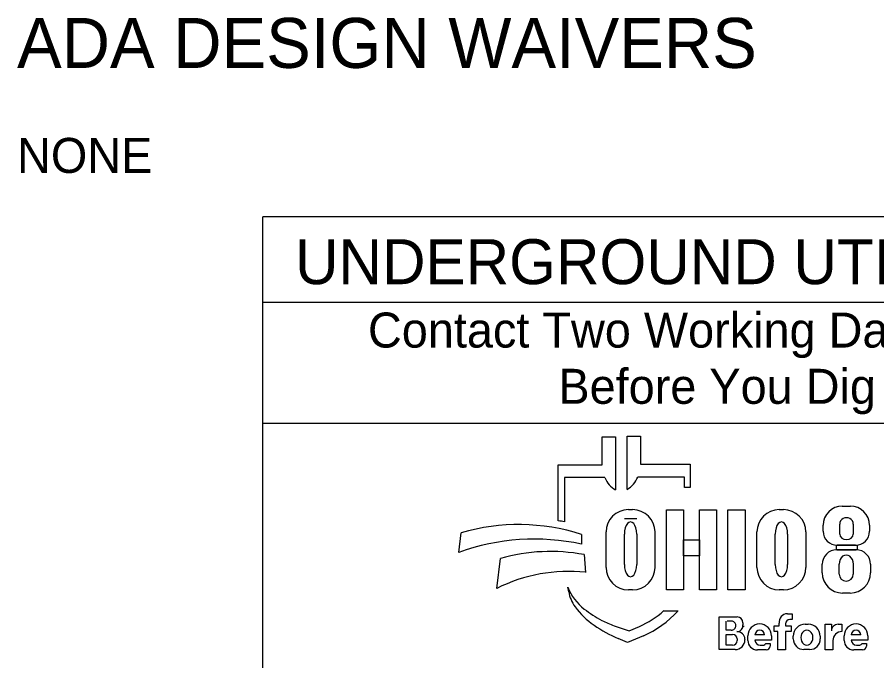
# Model space of a CAD drawing. Extents: x -59 to 82, y -3 to 49.
# Drawn here: x -55.003 to -51.567, y 31.095 to 33.67 of the extents above; entities that cross this region are included whole.
import ezdxf

# ---------------------------------------------------------------- set-up
doc = ezdxf.new("R2010")
doc.units = 0
doc.layers.add('SH_Data', color=7, linetype='Continuous')
doc.layers.add('SH_Text', color=7, linetype='Continuous')

msp = doc.modelspace()

# ---------------------------------------------------------------- linework, layer by layer
at = {"layer": 'SH_Data'}
for p, q in [((-54.0205, 30.534), (-54.0205, 32.8715)), ((-49.7705, 32.8715), (-54.0205, 32.8715)), ((-54.0205, 32.53), (-49.7705, 32.53)), ((-54.0205, 32.0466), (-49.7705, 32.0466))]:
    msp.add_line(p, q, dxfattribs=at)
at = {"layer": 'SH_Text'}
for p, q in [((-52.5651, 31.7813), (-52.5651, 31.9934)), ((-52.5651, 31.9934), (-52.5115, 31.9934)), ((-52.5115, 31.9934), (-52.5115, 31.8819)), ((-52.6644, 31.8795), (-52.6644, 31.991)), ((-52.6644, 31.991), (-52.6108, 31.991)), ((-52.6108, 31.991), (-52.6108, 31.779)), ((-52.8404, 31.6557), (-52.8404, 31.8795)), ((-52.8404, 31.8795), (-52.6644, 31.8795)), ((-52.5115, 31.8819), (-52.3123, 31.8819)), ((-52.3123, 31.8819), (-52.3123, 31.7881)), ((-52.8152, 31.8281), (-52.8152, 31.6513)), ((-52.654, 31.8281), (-52.8152, 31.8281)), ((-52.3355, 31.8304), (-52.5219, 31.8304)), ((-52.3355, 31.7881), (-52.3355, 31.8304)), ((-52.3123, 31.7881), (-52.3355, 31.7881)), ((-52.5595, 31.7004), (-52.5429, 31.7004)), ((-51.9564, 31.7004), (-51.9399, 31.7004)), ((-51.7049, 31.7144), (-51.6721, 31.7144)), ((-52.5262, 31.6633), (-52.576, 31.6633)), ((-51.7812, 31.6137), (-51.7812, 31.638)), ((-51.715, 31.6024), (-51.715, 31.6417)), ((-51.6609, 31.6417), (-51.6609, 31.6024)), ((-51.5958, 31.638), (-51.5958, 31.6137)), ((-53.2378, 31.5294), (-53.2284, 31.6075)), ((-52.7471, 31.601), (-52.7471, 31.5622)), ((-52.6489, 31.4689), (-52.6489, 31.6109)), ((-52.576, 31.4803), (-52.576, 31.6026)), ((-52.5262, 31.6026), (-52.5262, 31.4803)), ((-52.4535, 31.6109), (-52.4535, 31.4689)), ((-52.0459, 31.4689), (-52.0459, 31.6109)), ((-51.973, 31.4803), (-51.973, 31.6026)), ((-51.9232, 31.6026), (-51.9232, 31.4803)), ((-51.8504, 31.6109), (-51.8504, 31.4689)), ((-51.6518, 31.5578), (-51.7252, 31.5578)), ((-52.7371, 31.5204), (-52.7309, 31.4494)), ((-51.727, 31.5394), (-51.6497, 31.5394)), ((-53.0859, 31.3848), (-53.0713, 31.505)), ((-51.7849, 31.4475), (-51.7849, 31.4816)), ((-51.7174, 31.4416), (-51.7174, 31.4825)), ((-51.6606, 31.4825), (-51.6606, 31.4416)), ((-51.5918, 31.4816), (-51.5918, 31.4475)), ((-52.7983, 31.3719), (-52.8013, 31.3898)), ((-52.5429, 31.3794), (-52.5595, 31.3794)), ((-51.9399, 31.3794), (-51.9564, 31.3794)), ((-51.6728, 31.3666), (-51.7039, 31.3666)), ((-52.418, 31.296), (-52.3605, 31.296)), ((-52.1967, 31.1403), (-52.1967, 31.271)), ((-52.1967, 31.271), (-52.1255, 31.271)), ((-51.9241, 31.2838), (-51.9046, 31.2838)), ((-51.9046, 31.2838), (-51.9046, 31.2608)), ((-52.1687, 31.2175), (-52.1687, 31.2545)), ((-52.1435, 31.2545), (-52.1648, 31.2545)), ((-52.1017, 31.2473), (-52.1017, 31.2394)), ((-51.9574, 31.2354), (-51.9574, 31.2459)), ((-51.9313, 31.2439), (-51.9313, 31.2354)), ((-51.9046, 31.2603), (-51.9148, 31.2603)), ((-51.8529, 31.242), (-51.8407, 31.242)), ((-51.7726, 31.1391), (-51.7726, 31.2418)), ((-51.7726, 31.2418), (-51.7481, 31.2418)), ((-51.7481, 31.2418), (-51.7481, 31.2149)), ((-51.7208, 31.2418), (-51.7069, 31.2418)), ((-51.7069, 31.2418), (-51.7069, 31.2121)), ((-52.6164, 31.2357), (-52.557, 31.2152)), ((-52.557, 31.2152), (-52.5159, 31.233)), ((-52.1493, 31.2175), (-52.1687, 31.2175)), ((-51.9767, 31.2124), (-51.9767, 31.2354)), ((-51.9767, 31.2354), (-51.9574, 31.2354)), ((-51.9618, 31.2124), (-51.9767, 31.2124)), ((-51.9618, 31.1391), (-51.9618, 31.2124)), ((-51.9313, 31.2354), (-51.9097, 31.2354)), ((-51.9097, 31.2124), (-51.9313, 31.2124)), ((-51.9313, 31.2124), (-51.9313, 31.1391)), ((-51.9097, 31.2354), (-51.9097, 31.2124)), ((-52.563, 31.1682), (-52.6003, 31.1846)), ((-52.4997, 31.1956), (-52.563, 31.1682)), ((-52.1687, 31.1581), (-52.1687, 31.201)), ((-52.1687, 31.201), (-52.1432, 31.201)), ((-52.125, 31.1829), (-52.125, 31.1765)), ((-52.0937, 31.18), (-52.0937, 31.1796)), ((-52.0821, 31.1771), (-52.0821, 31.1955)), ((-52.0155, 31.1995), (-52.0541, 31.1995)), ((-51.9876, 31.1778), (-52.054, 31.1778)), ((-51.9876, 31.1955), (-51.9876, 31.1778)), ((-51.9007, 31.1834), (-51.9007, 31.1942)), ((-51.7929, 31.1942), (-51.7929, 31.1834)), ((-51.7421, 31.1772), (-51.7421, 31.1391)), ((-51.6972, 31.1771), (-51.6972, 31.1955)), ((-51.6306, 31.1995), (-51.6692, 31.1995)), ((-51.6027, 31.1778), (-51.6691, 31.1778)), ((-51.6027, 31.1955), (-51.6027, 31.1778)), ((-52.133, 31.1403), (-52.1967, 31.1403)), ((-52.1434, 31.1581), (-52.1687, 31.1581)), ((-52.0088, 31.1391), (-52.0442, 31.1391)), ((-52.0331, 31.1586), (-52.019, 31.1586)), ((-52.0104, 31.1641), (-51.9935, 31.1641)), ((-51.9935, 31.1641), (-51.9935, 31.1543)), ((-51.9313, 31.1391), (-51.9618, 31.1391)), ((-51.8357, 31.1406), (-51.8579, 31.1406)), ((-51.7421, 31.1391), (-51.7726, 31.1391)), ((-51.6238, 31.1391), (-51.6592, 31.1391)), ((-51.6482, 31.1586), (-51.6341, 31.1586)), ((-51.6255, 31.1641), (-51.6086, 31.1641)), ((-51.6086, 31.1641), (-51.6086, 31.1543))]:
    msp.add_line(p, q, dxfattribs=at)
for points in [[(-52.407, 31.6993), (-52.3391, 31.6993), (-52.3391, 31.3793), (-52.407, 31.3793)], [(-52.2749, 31.6993), (-52.2069, 31.6993), (-52.2069, 31.3793), (-52.2749, 31.3793)], [(-52.1616, 31.6993), (-52.0928, 31.6993), (-52.0928, 31.3793), (-52.1616, 31.3793)], [(-52.3391, 31.5794), (-52.2749, 31.5794), (-52.2749, 31.5154), (-52.3391, 31.5154)], [(-51.7273, 31.5578), (-51.6457, 31.5578), (-51.6457, 31.5393), (-51.7273, 31.5393)]]:
    msp.add_lwpolyline(points, close=True, dxfattribs=at)
for centre, radius, start, end in [((-52.5627, 31.8649), 0.0985, 201.9296, 240.7469), ((-52.6133, 31.8672), 0.0985, 299.2531, 338.0704), ((-52.5595, 31.6109), 0.0895, 90, 180), ((-52.5429, 31.6109), 0.0895, 0, 90), ((-51.9564, 31.6109), 0.0895, 90, 180), ((-51.9399, 31.6109), 0.0895, 0, 90), ((-51.7049, 31.638), 0.0763, 90, 180), ((-51.6721, 31.638), 0.0763, 0, 90), ((-52.9685, 30.8467), 0.8191, 79.2074, 81.0007), ((-52.9983, 30.8214), 0.8191, 72.1402, 106.3144), ((-52.9352, 30.6903), 0.8919, 77.8238, 109.8274), ((-51.7252, 31.6137), 0.056, 180, 270), ((-51.6518, 31.6137), 0.056, 270, 0), ((-52.8713, 30.8006), 0.7322, 79.44, 105.8467), ((-51.727, 31.4816), 0.0579, 90, 180), ((-51.6497, 31.4816), 0.0579, 0, 90), ((-52.7993, 30.8174), 0.6357, 83.8248, 116.8021), ((-52.5595, 31.4689), 0.0895, 180, 270), ((-52.5429, 31.4689), 0.0895, 270, 0), ((-51.9564, 31.4689), 0.0895, 180, 270), ((-51.9399, 31.4689), 0.0895, 270, 0), ((-51.7039, 31.4475), 0.081, 180, 270), ((-51.6728, 31.4475), 0.081, 270, 0), ((-52.6139, 31.4619), 0.2008, 201.0457, 232.5314), ((-52.657, 31.396), 0.1433, 189.6817, 216.0884), ((-52.5233, 31.4935), 0.3088, 216.0884, 235.7167), ((-52.4214, 31.7132), 0.5173, 232.5314, 241.794), ((-52.6593, 31.5635), 0.3602, 293.4582, 312.0712), ((-52.6593, 31.5635), 0.401, 293.4582, 317.8286), ((-52.1255, 31.2473), 0.0238, 0, 90), ((-51.9241, 31.2503), 0.0335, 90, 187.5187), ((-52.3568, 31.7377), 0.6044, 235.7167, 246.2325), ((-52.5066, 31.5544), 0.3371, 241.794, 250.9821), ((-52.1493, 31.2363), 0.0187, 270, 2.0582), ((-52.1474, 31.2376), 0.0169, 357.8325, 90), ((-52.1259, 31.2365), 0.0243, 270, 6.6529), ((-52.0349, 31.1955), 0.0473, 0, 180), ((-51.9148, 31.2439), 0.0165, 90, 180), ((-51.8529, 31.1942), 0.0478, 90, 180), ((-51.8407, 31.1942), 0.0478, 0, 90), ((-51.7212, 31.2149), 0.0269, 89.2449, 180), ((-51.6499, 31.1955), 0.0473, 0, 180), ((-52.1258, 31.1801), 0.0321, 4.0748, 90), ((-52.1153, 31.2351), 0.0175, 347.4023, 0), ((-52.0348, 31.1985), 0.0193, 2.9632, 177.0368), ((-51.7072, 31.1772), 0.0349, 89.6033, 180), ((-51.6499, 31.1985), 0.0193, 2.9632, 177.0368), ((-52.1434, 31.1765), 0.0184, 270, 0), ((-52.1432, 31.1829), 0.0181, 0, 90), ((-52.133, 31.1796), 0.0393, 270, 0), ((-52.1266, 31.18), 0.033, 0, 11.7502), ((-52.0442, 31.1771), 0.038, 180, 270), ((-52.0331, 31.1796), 0.021, 184.827, 270), ((-51.8579, 31.1834), 0.0428, 180, 270), ((-51.8357, 31.1834), 0.0428, 270, 0), ((-51.6592, 31.1771), 0.038, 180, 270), ((-51.6482, 31.1796), 0.021, 184.827, 270), ((-52.019, 31.168), 0.00938, 270, 335.9979), ((-52.0088, 31.1543), 0.0152, 270, 0), ((-51.6341, 31.168), 0.00938, 270, 335.9979), ((-51.6238, 31.1543), 0.0152, 270, 0)]:
    msp.add_arc(centre, radius, start, end, dxfattribs=at)
for centre, major_axis, ratio, start_param, end_param in [((-52.5511, 31.6026), (0, 0.0484), 0.514403, 4.712389, 7.853982), ((-51.9481, 31.6026), (0, 0.0484), 0.514403, 4.712389, 7.853982), ((-51.688, 31.6417), (0.0271, 0), 0.969373, 0, 3.141593), ((-51.688, 31.6024), (0.0271, 0), 0.818453, 3.141593, 6.283185), ((-51.689, 31.4825), (0, 0.0358), 0.794529, 4.712389, 7.853982), ((-52.5511, 31.4803), (0, 0.0484), 0.514403, 1.570796, 4.712389), ((-51.9481, 31.4803), (0, 0.0484), 0.514403, 1.570796, 4.712389), ((-51.689, 31.4416), (0.0284, 0), 0.959837, 3.141593, 6.283185), ((-51.8463, 31.1888), (0, 0.029), 0.832186, 4.712389, 7.853982), ((-51.8463, 31.1888), (0, 0.0302), 0.797287, 1.570796, 4.712389)]:
    msp.add_ellipse(centre, major_axis=major_axis, ratio=ratio, start_param=start_param, end_param=end_param, dxfattribs=at)

# ---------------------------------------------------------------- texts
for s, height, p in [('ADA DESIGN WAIVERS', 0.2, (-55.0036, 33.4669)), ('NONE', 0.14, (-55.0036, 33.0469)), ('UNDERGROUND UTILITIES', 0.18, (-53.8923, 32.6019)), ('Contact Two Working Days', 0.14, (-53.6008, 32.3484)), ('Before You Dig', 0.14, (-52.8397, 32.1234))]:
    msp.add_text(s, height=height, dxfattribs=at).set_placement(p)

doc.saveas('drawing.dxf')
